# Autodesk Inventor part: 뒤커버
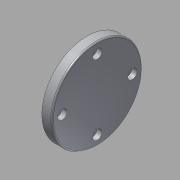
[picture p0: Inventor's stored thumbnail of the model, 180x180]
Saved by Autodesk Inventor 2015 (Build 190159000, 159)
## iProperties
Created: 2015-09
Part Number: 뒤커버
Material: 알루미늄 6061
Document SubType Name: Modeling
Designer: mduedu
Density: 1 g/cm^3
Appearance: 알루미늄 - 평지
Author: mduedu
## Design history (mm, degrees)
sketch "스케치1"
  geometry: L1 (-15.5, 47)-(-15.5, 78); L2 (-15.5, 78)-(-22.5, 78); L3 (-22.5, 78)-(-22.5, 67); L4 (-25.5, 67)-(-25.5, 47); L5 (-79.5, 39.5)-(-79.5, 54.5) reference; L6 (48.5, 54.5)-(48.5, 39.5) reference; L7 (-79.5, 47)-(48.5, 47); L8 (-22.5, 67)-(-25.5, 67); L9 (-25.5, 47)-(-15.5, 47); 1 further point
  constraints: 14 end point, 4 midpoint, 3 parallel, 1 collinear, 1 point on line, 1 vertical
  dimensions: "d6" = 62 diameter of L2 L7; "d7" = 7 distance of L1.end L2.end; "d8" = 40 diameter of L3.end L7; "d32" = 10 distance between parallel lines of L1 L4
revolve "회전1" sketch "스케치1" stored, may be unused: angle "d4" = 90 deg
sketch "스케치4"
  geometry: C1 r 31 at (0, 0) reference; 2 further points
  constraints: 1 coincident
hole "구멍3" sketch "스케치4" at (0, 0) diameter "d33" = 33; stored, may be unused: countersink angle "d37" = 90 deg, drill point angle "d39" = 0 deg; dims "d34" = 6, "d35" = 4, "d36" = 2, "d38" = 5
fillet "모깎기4" dims "d40" = 1
chamfer "모따기2" distance "d41" = 1; stored, may be unused: second distance "d42" = 2, angle "d43" = 45 deg
sketch "스케치5" dims "d44" = 48
  geometry: C1 r 31 at (0, 0) reference; 6 further points
  constraints: 2 vertical alignment, 1 coincident, 7 other
  dimensions: "d47" = 360 deg dimension on C1.centre point (0, -24) (derived)
sketch "스케치6"
  geometry: 4 further points
hole "구멍4" sketch "스케치6" at (24, 0), (0, 24), (-24, 0), (0, -24) diameter "d49" = 3.4; stored, may be unused: countersink angle "d53" = 90 deg, drill point angle "d55" = 0 deg; dims "d50" = 6, "d51" = 6.5, "d52" = 3.4, "d54" = 8
node "솔리드1"
node "참조1"
node "참조2"
